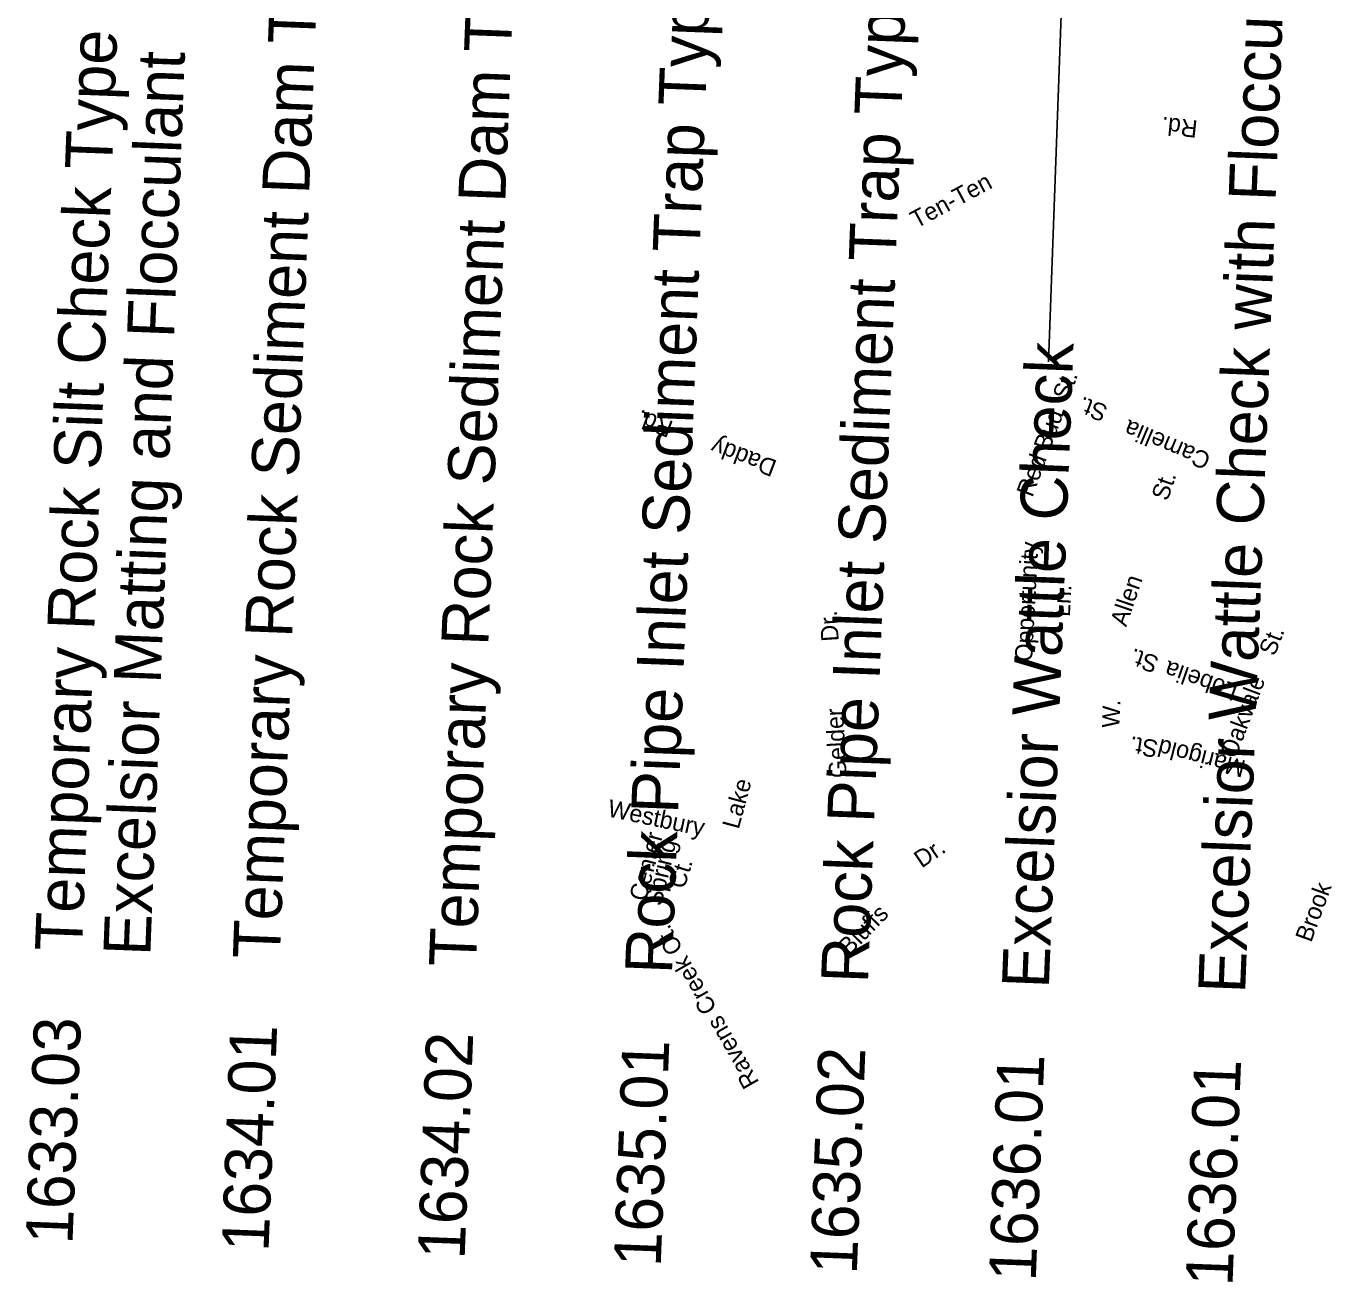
# Model space of a CAD drawing. Extents: x 1654773 to 2116434, y 680831 to 888488.
# Drawn here: x 2111725 to 2113608, y 697255 to 699067 of the extents above; entities that cross this region are included whole.
import ezdxf

# ---------------------------------------------------------------- set-up
doc = ezdxf.new("R2010")
doc.units = 0
for name, color, linetype in [('EC Title Sheet CELL', 7, 'Continuous'), ('Exist Road Non-System Type 51 Label', 7, 'Continuous'), ('Exist Road Secondary Type 51 Label', 7, 'Continuous')]:
    doc.layers.add(name, color=color, linetype=linetype)

msp = doc.modelspace()

# ---------------------------------------------------------------- linework, layer by layer
at = {"layer": 'EC Title Sheet CELL'}
msp.add_line((2113199.7, 698582.8), (2113235, 699552.9), dxfattribs=at)

# ---------------------------------------------------------------- texts
for s, height, p in [('Temporary Rock Silt Check Type A with', 67.828, (2111805, 697731.2)), ('Temporary Rock Sediment Dam Type A', 67.855, (2112090.5, 697720.2)), ('Temporary Rock Sediment Dam Type B', 67.828, (2112373.4, 697708.7)), ('Rock Pipe Inlet Sediment Trap Type A', 67.733, (2112656.2, 697698.5)), ('Rock Pipe Inlet Sediment Trap Type B', 67.733, (2112939, 697685.2)), ('Excelsior Wattle Check with Flocculant', 67.828, (2113483.2, 697670.5)), ('Excelsior Matting and Flocculant', 67.828, (2111903.6, 697724.6)), ('Excelsior Wattle Check', 67.828, (2113200, 697677.6)), ('1633.03', 67.74, (2111791.3, 697308.4)), ('1634.01', 67.74, (2112074.2, 697297.5)), ('1634.02', 67.74, (2112357.1, 697286.6)), ('1635.01', 67.74, (2112640, 697275.8)), ('1635.02', 67.74, (2112922.9, 697264.9)), ('1636.01', 67.74, (2113181.1, 697255)), ('1636.01', 67.74, (2113464.9, 697247.9))]:
    msp.add_text(s, height=height, rotation=87.802, dxfattribs=at).set_placement(p)
at = {"layer": 'Exist Road Non-System Type 51 Label'}
for s, height, rotation, p in [('Rd.', 25.05, 159.3052, (2112659.8, 698496)), ('Daddy', 25.05, 159.2796, (2112809.3, 698439.5)), ('Opportunity ', 25.049, 86.959, (2113175.8, 698149.5)), ('Ln.', 25.05, 86.959, (2113230.3, 698214.2)), ('Dr.', 25.05, 93.807, (2112897, 698179.8)), (' St.', 25.05, 68.5676, (2113522.3, 698148)), ('Oakvale', 25.05, 69.4726, (2113469.6, 698008.8)), ('Gelder', 25.05, 93.0762, (2112908.4, 697982.7))]:
    msp.add_text(s, height=height, rotation=rotation, dxfattribs=at).set_placement(p)
at = {"layer": 'Exist Road Secondary Type 51 Label'}
for s, height, rotation, p in [('Rd.', 25.05, 173.966, (2113415.6, 698930.9)), ('Ten-Ten', 25.05, 28.243, (2113008.9, 698774.8)), ('Red Bud  St.', 25.049, 69.5327, (2113176.1, 698386.1)), (' St.', 25.05, 159.6444, (2113295.5, 698515.6)), ('Camellia', 25.05, 157.1172, (2113435.5, 698449.1)), (' St.', 25.05, 71.1277, (2113368.2, 698371.9)), ('Allen', 25.05, 71.2588, (2113311.7, 698199.2)), (' St.', 25.05, 160.7368, (2113369.4, 698153.2)), ('Lobelia', 25.05, 160.7368, (2113474.5, 698116.2)), ('W.', 25.05, 87.6222, (2113301.6, 698053.9)), (' St.', 25.05, 170.8196, (2113368.2, 698034.4)), ('Marigold', 25.05, 165.4554, (2113485.5, 698006.6)), ('Lake', 25.05, 74.9008, (2112752.5, 697907.1)), ('Westbury', 25.05, 348.1507, (2112562.1, 697926.8)), ('Center', 25.05, 75.4953, (2112618.5, 697802.9)), ('Spring', 25.05, 76.8406, (2112641, 697796.1)), ('Dr.', 25.05, 34.1772, (2113016.5, 697851.3)), ('Ct.', 25.05, 72.6205, (2112674, 697820.7)), ('Brook', 25.05, 69.9351, (2113578.4, 697743.6)), ('Bluffs', 25.05, 45.6263, (2112912, 697724.5)), ('Ravens Creek Ct.', 25.049, 119.6771, (2112782.7, 697542.8))]:
    msp.add_text(s, height=height, rotation=rotation, dxfattribs=at).set_placement(p)

doc.saveas('drawing.dxf')
